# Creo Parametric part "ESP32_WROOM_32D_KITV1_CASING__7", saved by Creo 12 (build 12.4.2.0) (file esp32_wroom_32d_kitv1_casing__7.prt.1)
Units: Custom; MM, KILOGRAM, SECS

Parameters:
  PTC_WM_ITERATION = "0"
  PTC_WM_VERSION = "-.0"
  PTC_WM_LIFECYCLE_STATE = "In Work"
  PTC_WM_LIFECYCLE = "MO_CADDocument"
  PTC_WM_CREATED_BY = "Maximilian Roepper (Z0017RMS: MO)"
  PTC_WM_CREATED_ON = "18-Sep-26 11:36:42 AM"
  PTC_WM_MODIFIED_BY = "Maximilian Roepper (Z0017RMS: MO)"
  PTC_WM_MODIFIED_ON = "18-Sep-26 11:36:46 AM"
  PDMLINKNUMBER = "PDM000071454868"
  PTC_WM_NAME = "esp32_wroom_32d_kitv1_casing__7.prt"
  PTC_WM_NUMBER = "PDM000071454868"

Other parameters: WEIGHT, WEIGHT_FACTOR, WEIGHT_ADD, _MASS_TEMP, _DIFF_TEMP, MC_ERRORS, SUPPLIER

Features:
  1. coordinate system
  2. datum plane "PRT_YZ"
  3. datum plane "PRT_XY"
  4. datum plane "PRT_XZ"
  5. coordinate system
  6. datum axis
  7. datum axis
  8. datum axis
  9. coordinate system
  10. imported feature
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
Other named items: PRT, SIEMENS_MO, DRW_VIEW_ORG, PRT_X, PRT_Y, PRT_Z, CS0, ROUGH_GROB

Layers: 00_STD_CSYS-KSYS, 01_STD_PLANES-EBENEN, 02_STD_AXES-ACHSEN, 03_STD_CSYS-KSYS, 24_IMPORT_FEAT-IMPORT_KE

Surfaces: 6 plane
